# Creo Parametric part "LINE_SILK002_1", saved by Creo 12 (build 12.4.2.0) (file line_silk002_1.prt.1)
Units: Custom; MM, KILOGRAM, SECS

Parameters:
  PTC_WM_ITERATION = "0"
  PTC_WM_VERSION = "-.0"
  PTC_WM_LIFECYCLE_STATE = "In Work"
  PTC_WM_LIFECYCLE = "MO_CADDocument"
  PTC_WM_CREATED_BY = "Maximilian Roepper (Z0017RMS: MO)"
  PTC_WM_CREATED_ON = "18-Sep-26 11:36:42 AM"
  PTC_WM_MODIFIED_BY = "Maximilian Roepper (Z0017RMS: MO)"
  PTC_WM_MODIFIED_ON = "18-Sep-26 11:36:46 AM"
  PDMLINKNUMBER = "PDM000071454843"
  PTC_WM_NAME = "line_silk002_1.prt"
  PTC_WM_NUMBER = "PDM000071454843"

Other parameters: WEIGHT, WEIGHT_FACTOR, WEIGHT_ADD, _MASS_TEMP, _DIFF_TEMP, MC_ERRORS, SUPPLIER

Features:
  1. coordinate system
  2. datum plane "PRT_YZ"
  3. datum plane "PRT_XY"
  4. datum plane "PRT_XZ"
  5. coordinate system
  6. datum axis
  7. datum axis
  8. datum axis
  9. coordinate system
  10. imported feature

Other named items: PRT, SIEMENS_MO, DRW_VIEW_ORG, PRT_X, PRT_Y, PRT_Z, CS0, ROUGH_GROB

Layers: 00_STD_CSYS-KSYS, 01_STD_PLANES-EBENEN, 02_STD_AXES-ACHSEN, 03_STD_CSYS-KSYS, 24_IMPORT_FEAT-IMPORT_KE

Surfaces: 8 plane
